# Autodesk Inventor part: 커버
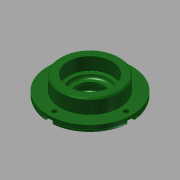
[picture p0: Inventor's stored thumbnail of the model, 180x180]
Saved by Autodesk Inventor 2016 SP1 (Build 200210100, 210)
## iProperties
Company: 한국ATC센터
Created: 2016-04
Part Number: 커버
Document SubType Name: Modeling
Designer: mdu
Density: 7.86 g/cm^3
Mass: 351.567 g
Surface Area: 161.165 cm^2
Volume: 44.7286 cm^3
Material: 강철, 연강
Appearance: 진녹색
Author: mdu
Revision Number: 1
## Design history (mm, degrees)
sketch "스케치1"
  geometry: C1 r 38 at (0, 0); 1 further point
  constraints: 1 centre point, 1 coincident
  dimensions: "d0" = 76 diameter of C1
extrude "돌출1" new body sketch "스케치1" distance "d1" = 7; taper "d2" = 0 deg
sketch "스케치2"
  geometry: C1 r 27 at (0, 0); 1 further point
  constraints: 1 centre point, 1 coincident
  dimensions: "d3" = 54 diameter of C1
extrude "돌출2" join sketch "스케치2" distance "d4" = 13; taper "d5" = 0 deg
sketch "스케치3"
  geometry: C1 r 20 at (0, 0); 1 further point
  constraints: 1 centre point, 1 coincident
  dimensions: "d6" = 40 diameter of C1
extrude "돌출3" join sketch "스케치3" distance "d7" = 5; taper "d8" = 0 deg
hole "구멍1" diameter "d11" = 25; stored, may be unused: countersink angle "d15" = 90 deg, drill point angle "d17" = 118 deg; dims "d9" = 10, "d10" = 10, "d12" = 6, "d13" = 32, "d14" = 8.3, "d16" = 8
hole "구멍2" diameter "d20" = 34; stored, may be unused: countersink angle "d24" = 90 deg, drill point angle "d26" = 0 deg; dims "d18" = 10, "d19" = 10, "d21" = 6, "d22" = 40, "d23" = 12, "d25" = 3
fillet "모깎기2" dims "d34" = 3
fillet "모깎기1" dims "d27" = 0.3
chamfer "모따기1" distance "d28" = 1; stored, may be unused: second distance "d29" = 2, angle "d30" = 45 deg
chamfer "모따기2" distance "d31" = 1.2; stored, may be unused: second distance "d32" = 2, angle "d33" = 30 deg
sketch "스케치4" dims "d35" = 65
  geometry: 3 further points
  constraints: 2 horizontal alignment, 1 coincident, 2 other
hole "구멍3" sketch "스케치4" at (32.5, 0) diameter "d36" = 4.5; stored, may be unused: countersink angle "d40" = 90 deg, drill point angle "d42" = 118 deg; dims "d37" = 6, "d38" = 8, "d39" = 4.4, "d41" = 13
sketch "스케치5"
  geometry: L1 (0, 4)-(5.5, 4); L2 (5.5, 4)-(5.5, -4); L3 (5.5, -4)-(0, -4); L4 (0, -4)-(0, 4); C1 r 2.25 at (0, 0) reference; C2 r 38 at (-32.5, 0) reference; 2 further points
  constraints: 8 end point, 3 horizontal, 2 parallel, 1 perpendicular, 1 tangent, 1 vertical alignment, 1 other
extrude "돌출4" cut sketch "스케치5" stored distance "d47" = 24.5; taper "d48" = 0 deg
node "솔리드1"
pattern_circular "원형 패턴1" dims angle "d44" = 360 deg
pattern_circular "원형 패턴2" dims angle "d50" = 360 deg
node "투영된 루프1"
